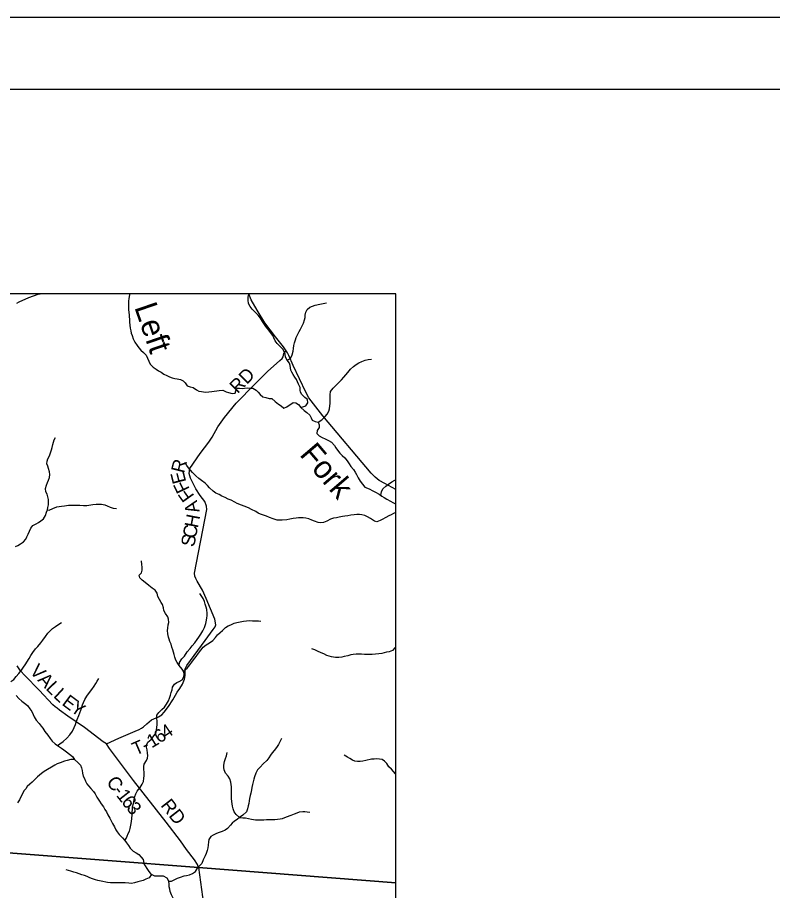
# Model space of a CAD drawing. Extents: x -139 to 835, y 0 to 440.
# Drawn here: x 242.7 to 348, y 318.3 to 440 of the extents above; entities that cross this region are included whole.
import ezdxf

# ---------------------------------------------------------------- set-up
doc = ezdxf.new("R2010")
doc.units = 0
for name, color, linetype in [('GM_X_County_Road', 7, 'Continuous'), ('GM_X_County_Road_Text', 7, 'Continuous'), ('GM_X_County_Text', 7, 'Continuous'), ('GM_X_Minor_River', 7, 'Continuous'), ('GM_X_Minor_River_Text', 7, 'Continuous'), ('GM_X_State_Route', 7, 'Continuous'), ('GM_X_Township_Road', 7, 'Continuous'), ('GM_X_Township_Road_Text', 7, 'Continuous'), ('SH_Border', 7, 'Continuous'), ('SH_Cut_Line', 7, 'Continuous')]:
    doc.layers.add(name, color=color, linetype=linetype)

msp = doc.modelspace()

# ---------------------------------------------------------------- linework, layer by layer
at = {"layer": 'GM_X_County_Road'}
for points in [[(295.46, 374.19), (293.94, 375.02), (293.15, 375.48), (292.58, 375.92), (291.99, 376.47), (285.26, 384.49), (283.3, 386.97), (282.9, 387.76), (281.12, 391.49), (280.55, 392.9), (280.34, 393.26), (280.16, 393.51), (279.79, 394.07), (278.68, 395.47), (277.2, 397.44), (276.13, 399.18), (275.27, 400.64), (274.97, 401.49)], [(255.08, 338.76), (254.64, 339.05), (252.01, 341.03), (249.7, 342.63), (248.55, 343.45), (248.2, 343.73), (247.92, 343.92), (247.63, 344.21), (245.72, 346.24), (243.7, 348.29), (243.13, 348.92), (242.66, 349.64)], [(267.92, 321.52), (267.8, 321.94), (267.39, 322.6), (266.28, 324.04), (265.4, 325.23), (263.43, 327.83), (258.85, 333.66), (255.53, 338.11), (255.08, 338.76)], [(267.92, 321.52), (268.51, 317.42), (269.15, 314.52), (270.02, 310.41), (270.49, 307.75)]]:
    msp.add_lwpolyline(points, dxfattribs=at)
at = {"layer": 'GM_X_County_Text'}
msp.add_lwpolyline([(295.46, 319.38), (295.46, 401.49), (205.14, 401.49), (203.62, 399.15), (203.28, 397.97), (203.25, 397.37), (203.29, 397.15), (203.08, 396.69), (187.01, 361.69), (186.62, 361.27), (186.29, 360.95), (186.02, 360.33), (185.9, 359.82), (185.73, 359.05), (185.38, 358.36), (184.77, 357.38), (172.32, 330.67), (171.56, 329.03), (177.15, 328.58), (194.29, 327.18), (207.44, 326.1), (228.15, 324.57), (267.91, 321.54)], close=True, dxfattribs=at)
msp.add_lwpolyline([(138.4, 185.39), (295.46, 185.39), (295.46, 319.38), (267.91, 321.54), (228.15, 324.57)], dxfattribs=at)
at = {"layer": 'GM_X_Minor_River'}
for points in [[(258.34, 401.49), (258.31, 401.33), (258.22, 400.83), (258.18, 400.47), (258.16, 400.1), (258.15, 399.72), (258.18, 399.3), (258.21, 398.88), (258.24, 398.55), (258.28, 398.25), (258.3, 397.95), (258.33, 397.53), (258.35, 397.13), (258.42, 396.68), (258.48, 396.3), (258.54, 395.98), (258.67, 395.65), (258.83, 395.21), (259.04, 394.73), (259.38, 394.28), (259.63, 393.95), (259.91, 393.64), (260.28, 393.29), (260.61, 392.91), (260.84, 392.51), (261.02, 392.08), (261.19, 391.69), (261.59, 391.25), (262.02, 391), (262.35, 390.75), (262.71, 390.54), (263.1, 390.29), (263.51, 390.08), (263.9, 389.92), (264.24, 389.79), (264.64, 389.67), (264.97, 389.61), (265.41, 389.53), (265.78, 389.37), (266.07, 389.06), (266.33, 388.65), (266.78, 388.5), (267.21, 388.43), (267.67, 388.1), (268, 387.92), (268.36, 387.85), (268.89, 387.79), (269.39, 387.84), (269.78, 387.88), (270.13, 387.93), (270.51, 387.97), (270.83, 388), (271.32, 388.05), (271.78, 387.84), (272.11, 387.71), (272.62, 387.59), (273.05, 387.65), (273.15, 387.97), (273.3, 388.31), (273.66, 388.35), (274, 388.29), (274.37, 388.33), (274.73, 388.36), (275.07, 388.34), (275.49, 388.32), (275.98, 388.07), (276.26, 387.76), (276.51, 387.44), (276.89, 387.14), (277.34, 387.01), (277.79, 386.9), (278.14, 386.87), (278.63, 386.48), (279.11, 386.1), (279.46, 385.86), (279.84, 385.55), (280.25, 385.74), (281.15, 386.31), (281.49, 386.27), (281.86, 386.03), (282.22, 385.64), (282.66, 385.2), (283.06, 384.96), (283.44, 384.58), (283.65, 384.21), (283.8, 383.86), (284.21, 383.7), (284.64, 383.58), (284.77, 383.24), (284.76, 382.83), (284.48, 382.45), (284.45, 382.02), (284.78, 381.67), (285.2, 381.45)], [(282.22, 385.64), (282.88, 385.87), (283.16, 386.29), (283.15, 386.73), (282.77, 387.04), (282.33, 387.43), (282.18, 387.75), (282.13, 388.06), (282.11, 388.4), (281.9, 388.88), (281.74, 389.2), (281.58, 389.54), (281.37, 389.87), (281.13, 390.22), (280.96, 390.56), (280.83, 390.86), (280.76, 391.17), (280.71, 391.47), (280.6, 391.8), (280.28, 392.21), (280.08, 392.67), (280.01, 393.06), (279.87, 393.44), (279.7, 393.75), (279.39, 394.11), (278.92, 394.57), (278.64, 394.92), (278.46, 395.35), (278.28, 395.68), (277.97, 396.11), (277.73, 396.42), (277.33, 396.91), (277.04, 397.32), (276.85, 397.64), (276.57, 398.08), (276.23, 398.52), (275.83, 398.9), (275.43, 399.34), (275.12, 399.73), (274.91, 400.13), (274.86, 400.6), (274.87, 401.03), (274.97, 401.43), (274.98, 401.49)], [(280.28, 392.21), (280.75, 392.46), (281, 392.98), (281.15, 393.47), (281.18, 393.87), (281.24, 394.29), (281.33, 394.67), (281.45, 395.08), (281.57, 395.41), (281.74, 395.77), (281.99, 396.25), (282.14, 396.57), (282.39, 397), (282.56, 397.39), (282.73, 397.85), (282.8, 398.2), (282.83, 398.5), (282.92, 398.91), (283.09, 399.3), (283.46, 399.63), (283.82, 399.77), (284.22, 399.89), (284.85, 400.03), (285.3, 400.12), (285.77, 400.22)], [(284.64, 383.58), (285.14, 383.91), (285.59, 384.38), (285.86, 384.7), (286.09, 385.13), (286.21, 385.47), (286.25, 385.88), (286.28, 386.18), (286.3, 386.56), (286.28, 387.04), (286.3, 387.39), (286.36, 387.88), (286.71, 388.31), (287.03, 388.64), (287.43, 389.03), (287.88, 389.49), (288.19, 389.86), (288.49, 390.2), (288.76, 390.53), (289.12, 390.99), (289.56, 391.36), (289.9, 391.64), (290.29, 391.85), (290.7, 392.06), (291.17, 392.23), (291.59, 392.31), (292.04, 392.36)], [(242.4, 366.24), (242.74, 366.4), (243.13, 366.61), (243.54, 366.93), (243.83, 367.28), (243.97, 367.6), (244.16, 368), (244.53, 368.81), (244.85, 369.2), (245.28, 369.4), (245.62, 369.59), (245.96, 369.86), (246.3, 370.12), (246.58, 370.6), (246.73, 371.04), (246.86, 371.38), (246.94, 371.71), (246.99, 372.07), (247.03, 372.39), (247.01, 372.8), (246.93, 373.19), (246.82, 373.54), (246.63, 373.88), (246.59, 374.35), (246.74, 374.82), (246.89, 375.18), (247.02, 375.5), (247.15, 375.9), (247.21, 376.28), (247.16, 376.68), (247, 377.13), (246.91, 377.44), (246.79, 377.79), (246.82, 378.14), (246.93, 378.47), (247.13, 378.91), (247.27, 379.3), (247.44, 379.73), (247.52, 380.08), (247.62, 380.48), (247.72, 380.82), (247.82, 381.13), (247.98, 381.47)], [(285.2, 381.45), (285.58, 381.29), (286.07, 381.04), (286.49, 380.79), (286.91, 380.35), (287.1, 380.03), (287.34, 379.67), (287.66, 379.27), (287.98, 378.95), (288.32, 378.61), (288.67, 378.2), (288.96, 377.76), (289.19, 377.4), (289.53, 377.01), (289.78, 376.61), (289.97, 376.28), (290.22, 375.82), (290.5, 375.38), (290.79, 374.96), (291.14, 374.52), (291.48, 374.39), (291.81, 374.25), (292.17, 374.08), (292.63, 373.85), (293.11, 373.54), (293.48, 373.29), (293.81, 373.09), (294.21, 372.84), (294.69, 372.57), (295.05, 372.38), (295.4, 372.2), (295.46, 372.18)], [(295.46, 371.02), (295.14, 370.86), (294.82, 370.68), (294.48, 370.53), (294.07, 370.31), (293.57, 370.04), (293.25, 369.87), (292.8, 369.69), (292.46, 369.8), (291.91, 370.18), (291.49, 370.4), (291.15, 370.56), (290.72, 370.68), (290.37, 370.72), (290.02, 370.71), (289.66, 370.67), (289.2, 370.61), (288.77, 370.55), (288.34, 370.47), (288.02, 370.42), (287.55, 370.35), (287.19, 370.27), (286.75, 370.2), (286.32, 370.05), (285.83, 369.79), (285.37, 369.6), (284.97, 369.55), (284.6, 369.6), (284.12, 369.77), (283.74, 369.94), (283.34, 370.12), (282.91, 370.21), (282.55, 370.26), (282.22, 370.26), (281.89, 370.24), (281.57, 370.19), (281.13, 370.14), (280.69, 370.06), (280.23, 369.99), (279.62, 369.94), (279.27, 369.93), (278.92, 369.94), (278.35, 370.11), (277.85, 370.28), (277.43, 370.49), (276.6, 370.79), (276.25, 370.92), (275.91, 371.14), (275.31, 371.42), (274.9, 371.67), (274.31, 371.89), (273.95, 372), (273.33, 372.25), (272.99, 372.44), (272.47, 372.73), (272.07, 372.88), (271.64, 373.1), (271.2, 373.27), (270.82, 373.51), (270.37, 373.68), (269.97, 373.95), (269.48, 374.45), (269.18, 374.76), (268.88, 375.07), (268.36, 375.45), (268, 375.72), (267.56, 376.13), (267.08, 376.58), (266.81, 376.88), (266.54, 377.21), (266.3, 377.56), (266.09, 377.99)], [(293.48, 373.29), (293.38, 373.42), (293.47, 373.86), (293.63, 374.29), (294.06, 374.65), (294.45, 374.97), (294.88, 375.27), (295.31, 375.51), (295.46, 375.62)], [(246.86, 371.38), (247.12, 371.31), (247.61, 371.54), (248.18, 371.78), (248.81, 371.89), (249.24, 371.94), (249.78, 372.03), (250.36, 372.03), (251.06, 372.03), (251.38, 372.01), (251.9, 371.97), (252.35, 371.97), (253.18, 372.11), (253.67, 372.16), (254, 372.17), (254.42, 372.14), (254.86, 372.05), (255.21, 371.92), (255.63, 371.76), (256.04, 371.62), (256.49, 371.54)], [(257.68, 325.3), (257.83, 325.57), (257.98, 325.9), (258.13, 326.25), (258.29, 326.56), (258.41, 326.95), (258.51, 327.4), (258.6, 327.91), (258.63, 328.34), (258.66, 328.87), (258.69, 329.24), (258.72, 329.65), (258.75, 329.99), (258.85, 330.45), (258.95, 330.95), (259.06, 331.42), (259.18, 331.79), (259.38, 332.18), (259.8, 332.68), (260.09, 333.11), (260.28, 333.52), (260.33, 333.98), (260.36, 334.31), (260.34, 334.78), (260.31, 335.24), (260.3, 335.61), (260.37, 335.94), (260.66, 336.42), (260.81, 336.77), (260.85, 337.14), (260.83, 337.45), (260.76, 337.9), (260.69, 338.31), (260.72, 338.67), (260.85, 338.98), (261.31, 339.35), (261.58, 339.69), (261.9, 340.1), (262.02, 340.42), (262.14, 341.01), (262.17, 341.43), (262.15, 341.91), (262.11, 342.3), (262.1, 342.77), (262.38, 343.12), (262.81, 343.53), (263.18, 343.86), (263.48, 344.28), (263.74, 344.75), (263.87, 345.13), (264.01, 345.53), (264.12, 345.9), (264.24, 346.3), (264.3, 346.65), (264.59, 347.09), (264.91, 347.31), (265.23, 347.42), (265.66, 347.67), (265.9, 348.1), (265.94, 348.46), (265.87, 348.79), (265.66, 349.18), (265.23, 349.68), (264.97, 350.09), (264.79, 350.43), (264.64, 350.84), (264.53, 351.21), (264.44, 351.52), (264.34, 351.84), (264.23, 352.25), (264.14, 352.63), (263.95, 353.03), (263.82, 353.34), (263.75, 353.64), (263.64, 354.09), (263.62, 354.56), (263.64, 354.9), (263.72, 355.32), (263.78, 355.66), (263.76, 356.14), (263.65, 356.44), (263.35, 356.9), (263.12, 357.36), (263.05, 357.72), (262.9, 358.16), (262.74, 358.47), (262.5, 358.85), (262.26, 359.3), (262.15, 359.77), (261.87, 360.16), (261.46, 360.47), (261.01, 360.84), (260.49, 361.23), (260.08, 361.56), (259.75, 361.9), (259.65, 362.28), (259.98, 362.61), (260.08, 362.95), (260.06, 363.4), (260.01, 363.74), (259.97, 364.25)], [(265.23, 349.68), (265.28, 350.1), (265.61, 350.6), (265.96, 350.99), (266.36, 351.59), (266.78, 352.06), (267.07, 352.42), (267.41, 352.84), (267.74, 353.28), (267.97, 353.63), (268.28, 354.04), (268.55, 354.52), (268.77, 354.99), (268.94, 355.51), (269.06, 355.99), (269.11, 356.3), (269.13, 356.6), (269.15, 356.9), (269.08, 357.47), (269, 357.81), (268.86, 358.23), (268.76, 358.58), (268.58, 358.99), (268.4, 359.31), (268.12, 359.71)], [(241.78, 347.46), (242.2, 347.71), (242.51, 348.13), (242.87, 348.57), (243.26, 349.03), (243.54, 349.44), (243.76, 349.78), (244.33, 350.67), (244.54, 351.07), (244.85, 351.49), (245.22, 351.99), (245.51, 352.34), (245.93, 352.83), (246.23, 353.2), (246.6, 353.72), (246.94, 354.18), (247.27, 354.54), (247.59, 354.83), (247.98, 355.1), (248.43, 355.42), (248.84, 355.66)], [(265.87, 348.79), (266, 349.04), (266.37, 349.3), (266.73, 349.77), (266.99, 350.16), (267.23, 350.48), (267.59, 350.92), (267.94, 351.4), (268.27, 351.79), (268.6, 352.23), (269.01, 352.55), (269.45, 352.82), (269.95, 353.18), (270.32, 353.59), (270.6, 353.94), (270.95, 354.27), (271.3, 354.57), (271.68, 354.95), (272.08, 355.19), (272.43, 355.36), (272.91, 355.58), (273.28, 355.67), (273.74, 355.77), (274.22, 355.87), (274.61, 355.91), (275.03, 355.93), (275.44, 355.91), (275.8, 355.89), (276.28, 355.88), (276.63, 355.85)], [(295.46, 352.16), (295.32, 352.13), (295, 351.76), (294.54, 351.56), (294.16, 351.52), (293.48, 351.35), (293.06, 351.29), (292.64, 351.23), (292.17, 351.19), (291.71, 351.19), (291.06, 351.22), (290.67, 351.24), (290.29, 351.26), (289.91, 351.25), (289.51, 351.21), (289.18, 351.14), (288.74, 351.02), (288.25, 350.91), (287.92, 350.83), (287.49, 350.77), (287.02, 350.77), (286.47, 350.88), (285.85, 351.08), (285.43, 351.28), (285.04, 351.46), (284.55, 351.68), (284.17, 351.85), (283.76, 352)], [(248.27, 338.5), (248.59, 338.77), (249.04, 339.1), (249.58, 339.55), (249.98, 340.03), (250.34, 340.5), (250.6, 341.02), (250.76, 341.43), (250.89, 341.78), (251.03, 342.16), (251.24, 342.72), (251.36, 343.09), (251.5, 343.45), (251.64, 343.85), (251.75, 344.19), (251.91, 344.52), (252.09, 344.94), (252.37, 345.4), (252.74, 345.92), (253.06, 346.34), (253.36, 346.77), (253.61, 347.16), (253.81, 347.5), (254.02, 347.88)], [(242.48, 345.47), (242.89, 345.09), (243.31, 344.69), (243.66, 344.44), (244.08, 344.1), (244.41, 343.65), (244.68, 343.26), (244.87, 342.84), (245.01, 342.5), (245.29, 342.05), (245.7, 341.59), (245.99, 341.24), (246.21, 340.93), (246.51, 340.47), (246.93, 339.95), (247.23, 339.52), (247.54, 339.11), (247.93, 338.74), (248.27, 338.5), (248.82, 338.14), (249.17, 337.91), (249.53, 337.65), (249.96, 337.31), (250.36, 336.99), (250.65, 336.57), (251.08, 336.15), (251.47, 335.76), (251.62, 335.42), (251.7, 335.05), (251.77, 334.66), (251.84, 334.26), (252.03, 333.9), (252.17, 333.56), (252.34, 333.2), (252.57, 332.9), (252.93, 332.52), (253.28, 332.13), (253.51, 331.78), (253.74, 331.31), (254.14, 330.75), (254.38, 330.41), (254.67, 329.99), (254.89, 329.58), (255.1, 329.27), (255.29, 328.86), (255.58, 328.38), (255.76, 328.01), (255.92, 327.67), (256.21, 327.18), (256.41, 326.77), (256.58, 326.47), (256.85, 326.12), (257.35, 325.64), (257.68, 325.3), (257.91, 324.96), (258.16, 324.59), (258.4, 324.22), (258.83, 323.81), (259.26, 323.56), (259.59, 323.31), (259.95, 322.95), (260.21, 322.64), (260.33, 322.11)], [(279.49, 339.5), (279.28, 339.03), (279.1, 338.68), (278.8, 338.26), (278.49, 337.81), (278.19, 337.49), (277.96, 337.17), (277.75, 336.79), (277.46, 336.41), (276.96, 335.98), (276.51, 335.49), (276.18, 335.14), (275.94, 334.66), (275.72, 334.16), (275.64, 333.85), (275.55, 333.48), (275.45, 333.07), (275.37, 332.67), (275.31, 332.33), (275.21, 331.89), (275.14, 331.55), (275.04, 331.14), (275.02, 330.82), (274.96, 330.46), (274.87, 330.13), (274.75, 329.7), (274.62, 329.27), (274.1, 328.79), (273.67, 328.47), (273.32, 328.23), (272.97, 327.96), (272.65, 327.72), (272.41, 327.41), (271.98, 326.96), (271.66, 326.72), (271.23, 326.54), (270.82, 326.4), (270.42, 326.24), (269.99, 326.04), (269.67, 325.83), (269.35, 325.43), (269.33, 325.1), (269.27, 324.63), (269.22, 324.27), (269.15, 323.9), (268.99, 323.48), (268.84, 323.13), (268.6, 322.59), (268.38, 322.06), (267.85, 321.53)], [(273.67, 328.47), (273.19, 328.92), (272.91, 329.28), (272.75, 329.7), (272.68, 330.05), (272.63, 330.37), (272.57, 330.71), (272.55, 331.12), (272.54, 331.49), (272.52, 331.9), (272.53, 332.77), (272.51, 333.07), (272.44, 333.39), (272.29, 333.87), (272.08, 334.23), (271.68, 334.66), (271.49, 335.15), (271.45, 335.46), (271.46, 335.78), (271.57, 336.3), (271.71, 336.73), (271.82, 337.08), (271.93, 337.54)], [(290.12, 336.31), (289.75, 336.36), (289.42, 336.47), (289.03, 336.7), (288.7, 336.91), (288.26, 337.16)], [(250.65, 336.57), (250.12, 336.57), (249.63, 336.45), (249.24, 336.35), (248.64, 336.12), (248.23, 335.95), (247.91, 335.76), (247.45, 335.48), (246.86, 335.19), (246.41, 334.9), (246.05, 334.62), (245.49, 334.17), (245.06, 333.76), (244.72, 333.42), (244.39, 333.14), (244.06, 332.82), (243.87, 332.5), (243.57, 332.19), (243.37, 331.77), (243.15, 331.39), (242.97, 330.97), (242.69, 330.52)], [(295.46, 334.53), (295.39, 334.58), (295.12, 334.92), (294.86, 335.22), (294.48, 335.57), (294.18, 336.01), (293.88, 336.36), (293.53, 336.58), (293.17, 336.64), (292.82, 336.65), (292.45, 336.63), (292.04, 336.6), (291.28, 336.43), (290.84, 336.34), (290.46, 336.3), (290.12, 336.31)], [(273.67, 328.47), (274.12, 328.46), (274.47, 328.43), (274.9, 328.34), (275.34, 328.24), (275.86, 328.17), (276.24, 328.15), (276.57, 328.16), (277.04, 328.18), (277.4, 328.19), (277.77, 328.21), (278.19, 328.2), (278.6, 328.2), (278.94, 328.24), (279.3, 328.29), (279.64, 328.36), (280.19, 328.56), (280.85, 328.82), (281.31, 329), (281.67, 329.14), (282.04, 329.27), (282.46, 329.33), (282.78, 329.33), (283.11, 329.28), (283.45, 329.25)], [(264.75, 316.46), (264.62, 316.88), (264.42, 317.23), (264.15, 317.71), (263.99, 318.18), (263.94, 318.49), (263.86, 318.83), (263.82, 319.19), (263.79, 319.59), (263.54, 320.02), (263.06, 320.29), (262.64, 320.3), (262.19, 320.29), (261.85, 320.33), (261.4, 320.55), (261.05, 320.95), (260.79, 321.37), (260.33, 322.11)], [(263.79, 319.59), (264.15, 319.61), (264.56, 319.82), (265.02, 320.04), (265.44, 320.19), (265.91, 320.34), (266.24, 320.4), (266.66, 320.49), (267.1, 320.67), (267.51, 320.98), (267.85, 321.53)], [(261.4, 320.55), (261.04, 320.09), (260.6, 319.89), (260.2, 319.72), (259.83, 319.61), (259.48, 319.5), (259.02, 319.36), (258.57, 319.31), (258.23, 319.32), (257.71, 319.36), (257.36, 319.37), (256.91, 319.38), (256.45, 319.36), (256.1, 319.36), (255.68, 319.37), (255.25, 319.42), (254.36, 319.61), (253.89, 319.71), (253.55, 319.79), (253.15, 319.95), (252.76, 320.1), (252.42, 320.24), (252.01, 320.38), (251.68, 320.49), (251.28, 320.64), (250.94, 320.76), (250.53, 320.89), (250.12, 321), (249.78, 321.11), (249.46, 321.19)]]:
    msp.add_lwpolyline(points, dxfattribs=at)
at = {"layer": 'GM_X_State_Route'}
msp.add_lwpolyline([(242.61, 400.19), (242.91, 400.37), (244.29, 400.98), (245.55, 401.41), (245.86, 401.49)], dxfattribs=at)
at = {"layer": 'GM_X_Township_Road'}
msp.add_lwpolyline([(255.08, 338.76), (256.81, 339.53), (259.12, 340.52), (259.64, 340.76), (259.96, 340.94), (260.27, 341.11), (260.72, 341.53), (261.05, 341.82), (261.39, 342.09), (262.37, 342.52), (262.84, 342.82), (263.16, 343.18), (263.75, 343.95), (264.33, 344.91), (264.74, 345.56), (264.94, 345.94), (265.33, 346.47), (265.71, 347.05), (265.99, 347.78), (266.06, 348.26), (266.06, 348.71), (266.07, 349.19), (266.32, 349.67), (268.86, 353.15), (269.99, 354.71), (270.25, 355.05), (270.34, 355.35), (270.23, 356.11), (269.61, 357.55), (268.98, 359.01), (268.47, 360.16), (267.76, 361.43), (267.55, 361.81), (267.43, 362.14), (267.39, 362.54), (269.1, 371.43), (269.07, 371.9), (268.83, 372.53), (268.18, 373.35), (267.56, 374.29), (266.83, 375.8), (266.65, 376.42), (266.72, 377.14), (268.18, 379.21), (269.35, 380.8), (269.86, 381.52), (270.63, 382.94), (271.56, 384.26), (273.19, 386.25), (275.81, 388.89), (277.62, 390.69), (278.79, 391.76), (279.29, 392.19), (279.62, 392.45), (279.74, 392.71), (279.81, 393.14), (280.16, 393.51)], dxfattribs=at)
at = {"layer": 'SH_Border'}
msp.add_lwpolyline([(30, 430), (670, 430), (670, 10), (30, 10)], close=True, dxfattribs=at)
at = {"layer": 'SH_Cut_Line'}
for points in [[(0, 0), (680, 0), (680, 440), (0, 440)], [(295.46, 319.38), (295.46, 401.49), (67.58, 401.49), (67.58, 336.52), (92.49, 334.76), (105.67, 333.83), (158.44, 330.1), (160.69, 329.92), (171.56, 329.03), (177.15, 328.58), (194.29, 327.18), (207.44, 326.1), (228.15, 324.57), (267.91, 321.54)], [(67.58, 336.52), (67.58, 185.39), (295.46, 185.39), (295.46, 319.38), (267.91, 321.54), (228.15, 324.57), (207.44, 326.1), (194.29, 327.18), (177.15, 328.58), (171.56, 329.03), (160.69, 329.92), (158.44, 330.1), (105.67, 333.83), (92.49, 334.76)]]:
    msp.add_lwpolyline(points, close=True, dxfattribs=at)

# ---------------------------------------------------------------- texts
at = {"layer": 'GM_X_County_Road_Text'}
for s, height, rotation, p in [('V', 1.88, 313.6158, (244.29, 348.78)), ('A', 1.88, 313.6119, (245.41, 347.6)), ('L', 1.88, 313.8077, (246.54, 346.42)), ('L', 1.87, 317.4948, (247.59, 345.33)), ('E', 1.86, 323.1508, (248.77, 344.26)), ('Y', 1.86, 325.1137, (249.94, 343.38)), ('C', 1.89, 306.3377, (255, 333.41)), ('-', 1.89, 307.516, (255.92, 332.16)), ('1', 1.89, 307.9539, (256.39, 331.55)), ('6', 1.89, 308.3944, (257.09, 330.64)), ('RD', 1.886, 308.0381, (262.57, 330.16)), ('3', 1.88, 308.4995, (257.8, 329.75))]:
    msp.add_text(s, height=height, rotation=rotation, dxfattribs=at).set_placement(p)
at = {"layer": 'GM_X_Minor_River_Text'}
for s, height, rotation, p in [('Left', 3.168, 288.9112, (258.96, 399.63)), ('Fork', 3.137, 310.4988, (281.92, 379.03))]:
    msp.add_text(s, height=height, rotation=rotation, dxfattribs=at).set_placement(p)
at = {"layer": 'GM_X_Township_Road_Text'}
for s, height, rotation, p in [('RD', 1.876, 45.5766, (273.4, 387.48)), ('R', 1.9, 76.0244, (265.91, 376.38)), ('E', 1.9, 104.2852, (266.24, 375.28)), ('F', 1.9, 115.5236, (266.74, 374.26)), ('F', 1.89, 125.4562, (267.42, 373.32)), ('A', 1.9, 104.4152, (268.11, 371.14)), ('H', 1.9, 79.0071, (267.83, 368.75)), ('C', 1.9, 78.9933, (267.55, 367.29)), ('S', 1.9, 78.9897, (267.32, 366.1)), ('6', 1.85, 33.5487, (262.48, 338.75)), ('4', 1.85, 33.7349, (263.44, 339.39)), ('1', 1.85, 30.7778, (261.4, 338.11)), ('T', 1.83, 23.4507, (259.16, 337.1)), ('-', 1.83, 24.342, (260.48, 337.68))]:
    msp.add_text(s, height=height, rotation=rotation, dxfattribs=at).set_placement(p)

doc.saveas('drawing.dxf')
